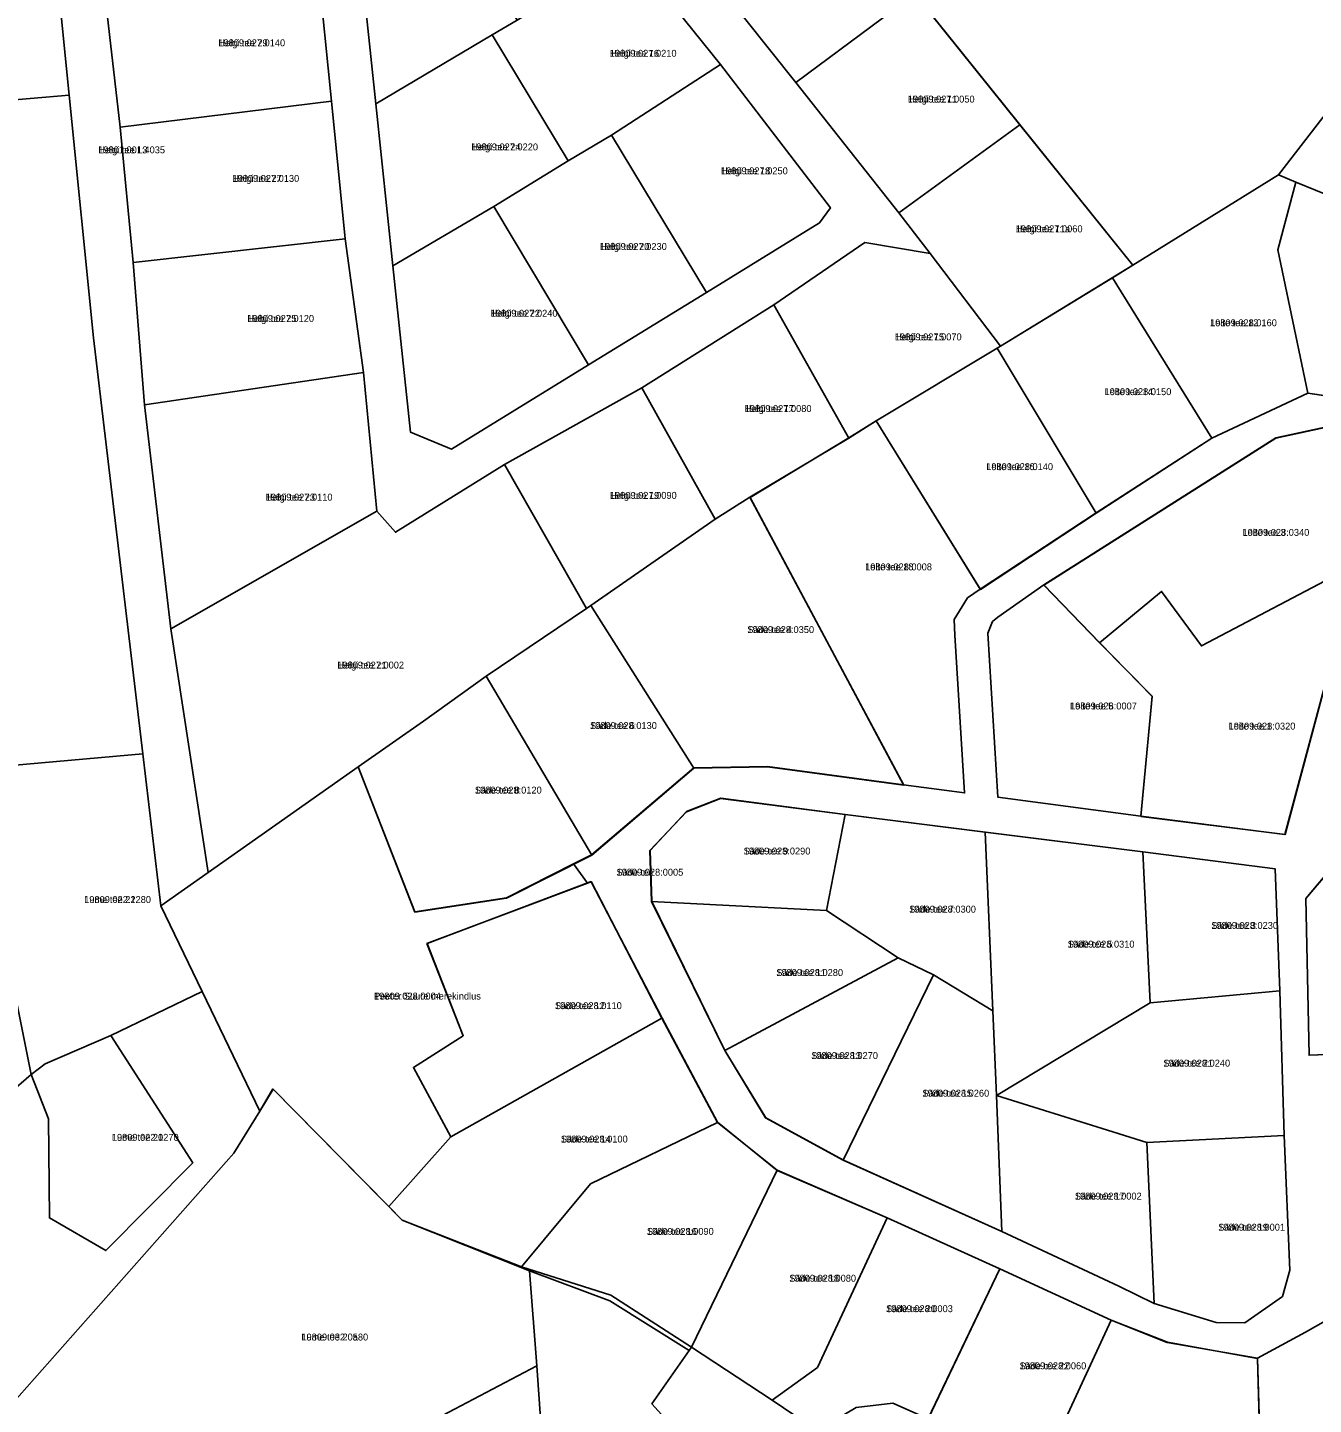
# Model space of a CAD drawing. Extents: x 516875 to 535633, y 6574491 to 6593094.
# Drawn here: x 521368.5 to 521647.7, y 6588659.7 to 6588958.5 of the extents above; entities that cross this region are included whole.
import ezdxf

# ---------------------------------------------------------------- set-up
doc = ezdxf.new("R2010")
doc.units = 0
for name, color, linetype in [('L_AADRESS', 7, 'Continuous'), ('PIIR', 7, 'Continuous'), ('TUNNUS', 7, 'Continuous')]:
    doc.layers.add(name, color=color, linetype=linetype)

msp = doc.modelspace()

# ---------------------------------------------------------------- linework, layer by layer
at = {"layer": 'PIIR'}
for points in [[(521590.91, 6589055.48), (521789.03, 6589241.93), (521800.17, 6589148.45), (521810.31, 6589063.39), (521810.89, 6589058.49), (521811.01, 6589057.49), (521738.69, 6588991.11), (521708.09, 6588956.45), (521702.42, 6588942.89), (521703.42, 6588925.56), (521710, 6588903.9), (521716.38, 6588894.74), (521673.79, 6588912.85), (521643.87, 6588925), (521640.14, 6588926.57), (521679.87, 6588978)], [(521359.99, 6589121.35), (521369.78, 6589120.47), (521372.96, 6589085.92), (521375.98, 6589055.84), (521381.13, 6589006.85), (521385.13, 6588967.12), (521388.61, 6588936.89), (521391.48, 6588907.51), (521393.88, 6588876.62), (521399.64, 6588828.05), (521407.72, 6588775.12), (521397.43, 6588767.88), (521393.53, 6588800.89), (521382.85, 6588891.18), (521377.57, 6588943.82), (521367.14, 6589047.69), (521365.58, 6589063.75)], [(521411.39, 6589116.77), (521436.47, 6589114.49), (521425.81, 6589100.81), (521428.46, 6589081.13), (521444.8, 6589060.34), (521467.91, 6589031.48), (521513.02, 6588974.62), (521535.33, 6588946.59), (521557.66, 6588918.34), (521564.46, 6588909.48), (521550.3, 6588911.88), (521530.56, 6588898.36), (521501.87, 6588880.36), (521472.1, 6588863.7), (521448.37, 6588849), (521444.33, 6588853.58), (521441.46, 6588883.67), (521437.48, 6588912.65), (521434.48, 6588942.56), (521431.53, 6588972.03), (521427.11, 6589012.43), (521422.52, 6589062.36), (521416.06, 6589093.87)], [(521432.07, 6589055.98), (521437.89, 6589000.93), (521444.12, 6588941.97), (521447.83, 6588906.81), (521451.64, 6588870.73), (521460.6, 6588867.04), (521490.33, 6588885.31), (521515.9, 6588901.02), (521540.48, 6588916.12), (521542.82, 6588919.42), (521518.97, 6588950.53), (521499.43, 6588974.81)], [(521526.07, 6589009.51), (521590.91, 6589055.48), (521679.87, 6588978), (521640.14, 6588926.57), (521608.51, 6588906.92)], [(521306.57, 6589051.13), (521305.68, 6589046.1), (521350.97, 6589047.31), (521367.14, 6589047.69), (521377.57, 6588943.82), (521360.53, 6588942.38), (521323.71, 6588953.19), (521318.95, 6588968.03), (521312.79, 6588965.96), (521301.69, 6589000.55), (521292.02, 6589012.37), (521274.46, 6589008.21), (521266.3, 6589048.24)], [(521469.37, 6588956.92), (521444.12, 6588941.97), (521437.89, 6589000.93), (521448.33, 6589003.56), (521474.81, 6588960.14)], [(521513.02, 6588974.62), (521538.41, 6588994.17), (521561.13, 6588965.84), (521535.33, 6588946.59)], [(521469.37, 6588956.92), (521474.81, 6588960.14), (521499.43, 6588974.81), (521518.97, 6588950.53), (521495.33, 6588935.2), (521485.91, 6588929.57)], [(521385.13, 6588967.12), (521431.53, 6588972.03), (521434.48, 6588942.56), (521388.61, 6588936.89)], [(521535.33, 6588946.59), (521561.13, 6588965.84), (521583.95, 6588937.4), (521557.66, 6588918.34)], [(521469.72, 6588919.66), (521447.83, 6588906.81), (521444.12, 6588941.97), (521469.37, 6588956.92), (521485.91, 6588929.57)], [(521542.82, 6588919.42), (521540.48, 6588916.12), (521515.9, 6588901.02), (521495.33, 6588935.2), (521518.97, 6588950.53)], [(521388.61, 6588936.89), (521434.48, 6588942.56), (521437.48, 6588912.65), (521391.48, 6588907.51)], [(521490.33, 6588885.31), (521469.72, 6588919.66), (521485.91, 6588929.57), (521495.33, 6588935.2), (521515.9, 6588901.02)], [(521564.46, 6588909.48), (521557.66, 6588918.34), (521583.95, 6588937.4), (521608.51, 6588906.92), (521579.74, 6588889.36)], [(521604.08, 6588904.23), (521608.51, 6588906.92), (521640.14, 6588926.57), (521643.87, 6588925), (521639.99, 6588910.31), (521646.47, 6588879.15), (521625.68, 6588869.42)], [(521639.99, 6588910.31), (521643.87, 6588925), (521673.79, 6588912.85), (521669.52, 6588901.71), (521667.19, 6588897.03), (521660, 6588877.16), (521646.47, 6588879.15)], [(521460.6, 6588867.04), (521451.64, 6588870.73), (521447.83, 6588906.81), (521469.72, 6588919.66), (521490.33, 6588885.31)], [(521391.48, 6588907.51), (521437.48, 6588912.65), (521441.46, 6588883.67), (521393.88, 6588876.62)], [(521546.83, 6588869.4), (521530.56, 6588898.36), (521550.3, 6588911.88), (521564.46, 6588909.48), (521579.74, 6588889.36), (521552.77, 6588873.18)], [(521579.05, 6588888.94), (521579.74, 6588889.36), (521604.08, 6588904.23), (521625.68, 6588869.42), (521600.56, 6588853.15)], [(521501.87, 6588880.36), (521530.56, 6588898.36), (521546.83, 6588869.4), (521525.34, 6588856.59), (521517.81, 6588851.8)], [(521579.05, 6588888.94), (521600.56, 6588853.15), (521575.4, 6588836.59), (521552.77, 6588873.18)], [(521441.46, 6588883.67), (521444.33, 6588853.58), (521399.64, 6588828.05), (521393.88, 6588876.62)], [(521489.85, 6588832.46), (521472.1, 6588863.7), (521501.87, 6588880.36), (521517.81, 6588851.8)], [(521525.38, 6588856.55), (521546.8, 6588869.5), (521552.8, 6588873.14), (521575.38, 6588836.66), (521572.61, 6588834.75), (521569.68, 6588830.02), (521569.88, 6588826.68), (521571.96, 6588792.41), (521558.73, 6588794.15)], [(521577.05, 6588827.11), (521579.21, 6588791.46), (521610.2, 6588787.38), (521641.5, 6588783.41), (521657.29, 6588842.15), (521662.14, 6588866.39), (521651.9, 6588872.14), (521639.52, 6588869.47), (521589.17, 6588837.56), (521579.18, 6588830.58), (521578.05, 6588829.6)], [(521614.73, 6588836.16), (521601.26, 6588825), (521589.2, 6588837.49), (521639.54, 6588869.44), (521651.92, 6588872.12), (521662.16, 6588866.37), (521657.31, 6588842.13), (521623.4, 6588824.31)], [(521444.33, 6588853.58), (521448.37, 6588849), (521472.1, 6588863.7), (521489.85, 6588832.46), (521468.09, 6588817.74), (521454.49, 6588808), (521440.28, 6588798.05), (521407.72, 6588775.12), (521399.64, 6588828.05)], [(521490.8, 6588833.12), (521517.81, 6588851.8), (521525.34, 6588856.59), (521558.79, 6588794.07), (521529.21, 6588798.04), (521513.2, 6588797.81)], [(521641.54, 6588783.37), (521610.26, 6588787.33), (521612.66, 6588813.39), (521601.26, 6588825), (521614.73, 6588836.16), (521623.4, 6588824.31), (521657.31, 6588842.13)], [(521577.05, 6588827.11), (521578.05, 6588829.6), (521579.18, 6588830.58), (521589.17, 6588837.56), (521601.3, 6588825), (521612.69, 6588813.36), (521610.2, 6588787.38), (521579.21, 6588791.46)], [(521489.85, 6588832.46), (521490.8, 6588833.12), (521513.2, 6588797.81), (521491.02, 6588778.91), (521468.09, 6588817.74)], [(521491.02, 6588778.91), (521472.54, 6588769.6), (521452.63, 6588766.54), (521440.28, 6588798.05), (521454.46, 6588807.99), (521468.09, 6588817.74)], [(521372.37, 6588733.63), (521369.27, 6588731.29), (521359.98, 6588777.57), (521355.22, 6588797.52), (521393.53, 6588800.89), (521397.43, 6588767.88), (521406.4, 6588749.3), (521386.6, 6588739.78)], [(521397.43, 6588767.88), (521407.72, 6588775.12), (521440.28, 6588798.05), (521452.61, 6588766.58), (521472.5, 6588769.67), (521487.08, 6588777.01), (521490.07, 6588772.84), (521455.24, 6588759.7), (521463.13, 6588739.7), (521452.28, 6588732.83), (521460.45, 6588717.77), (521446.98, 6588702.68), (521421.8, 6588728.17), (521418.94, 6588723.37), (521406.4, 6588749.3)], [(521503.62, 6588779.92), (521511.57, 6588788.32), (521519, 6588791.23), (521546.01, 6588787.73), (521541.99, 6588766.88), (521504.02, 6588768.83)], [(521503.67, 6588779.95), (521504.05, 6588768.86), (521519.92, 6588736.52), (521528.81, 6588721.93), (521545.64, 6588712.71), (521580.02, 6588697.24), (521605.49, 6588685.36), (521613.14, 6588681.58), (521626.57, 6588677.47), (521632.85, 6588677.42), (521641.02, 6588683.14), (521642.57, 6588688.8), (521641.35, 6588718.07), (521640.44, 6588749.43), (521639.42, 6588775.93), (521610.67, 6588779.61), (521576.48, 6588783.88), (521546.05, 6588787.74), (521519.04, 6588791.25), (521511.61, 6588788.35)], [(521557.58, 6588756.6), (521541.99, 6588766.88), (521546.01, 6588787.73), (521576.43, 6588783.88), (521578.13, 6588745.13), (521565.2, 6588752.91)], [(521578.13, 6588745.13), (521576.43, 6588783.88), (521610.64, 6588779.62), (521612.29, 6588746.83), (521578.9, 6588726.73)], [(521639.38, 6588775.96), (521640.41, 6588749.47), (521612.29, 6588746.83), (521610.64, 6588779.62)], [(521344.94, 6588771.8), (521359.98, 6588777.57), (521369.27, 6588731.29), (521364.46, 6588727.1), (521330.42, 6588734.26), (521334.54, 6588766.11)], [(521682.74, 6588774.72), (521682.56, 6588772.02), (521682.55, 6588762.98), (521683.71, 6588736.38), (521648.7, 6588735.54), (521646.75, 6588735.49), (521646.08, 6588769.53), (521651.82, 6588776.31)], [(521452.31, 6588732.82), (521463.11, 6588739.72), (521455.26, 6588759.73), (521490.88, 6588773.18), (521506.25, 6588743.51), (521460.42, 6588717.8)], [(521504.02, 6588768.83), (521541.99, 6588766.88), (521557.58, 6588756.6), (521519.88, 6588736.53)], [(521519.88, 6588736.53), (521557.58, 6588756.6), (521565.2, 6588752.91), (521545.6, 6588712.71), (521528.77, 6588721.9)], [(521578.13, 6588745.13), (521578.9, 6588726.73), (521580.02, 6588697.24), (521545.6, 6588712.71), (521565.2, 6588752.91)], [(521602.98, 6588719.25), (521578.9, 6588726.73), (521612.29, 6588746.83), (521640.41, 6588749.47), (521641.35, 6588718.07), (521611.51, 6588716.55)], [(521449.85, 6588699.7), (521446.95, 6588702.66), (521460.42, 6588717.8), (521506.25, 6588743.51), (521518.32, 6588720.88), (521490.75, 6588707.55), (521475.75, 6588689.57)], [(521404.37, 6588712.11), (521385.53, 6588693.09), (521373.28, 6588700.18), (521373.03, 6588721.65), (521369.27, 6588731.29), (521372.37, 6588733.63), (521386.6, 6588739.78)], [(521413.29, 6588714.19), (521418.94, 6588723.37), (521421.81, 6588728.14), (521449.85, 6588699.7), (521477.52, 6588688.69), (521479.07, 6588668.07), (521414.43, 6588634.08), (521384.67, 6588618.99), (521384.19, 6588619.81), (521361.62, 6588655.9)], [(521578.9, 6588726.73), (521602.98, 6588719.25), (521611.51, 6588716.55), (521613.14, 6588681.58), (521605.49, 6588685.36), (521580.02, 6588697.24)], [(521475.75, 6588689.57), (521490.75, 6588707.55), (521518.32, 6588720.88), (521531.26, 6588710.52), (521512.66, 6588672.12), (521495.17, 6588683.38)], [(521611.51, 6588716.55), (521641.35, 6588718.07), (521642.57, 6588688.8), (521641.02, 6588683.14), (521632.85, 6588677.42), (521626.57, 6588677.47), (521613.14, 6588681.58)], [(521512.66, 6588672.12), (521531.26, 6588710.52), (521555.15, 6588700.16), (521540.05, 6588667.74), (521530.2, 6588660.59)], [(521555.15, 6588700.16), (521579.64, 6588689.1), (521564.06, 6588656.54), (521556.42, 6588659.95), (521548.45, 6588659.06), (521537.94, 6588652.79), (521535.14, 6588657.27), (521530.2, 6588660.59), (521540.06, 6588667.73)], [(521486.87, 6588584.33), (521482.75, 6588615.48), (521479.07, 6588668.07), (521477.52, 6588688.69), (521494.97, 6588682.17), (521512.17, 6588671.42), (521504.07, 6588659.84), (521555.23, 6588603.22), (521567.46, 6588590.61), (521569.21, 6588585.96), (521555.19, 6588573.17), (521551.79, 6588559.93), (521542.52, 6588561.47), (521490.64, 6588555.41)], [(521579.64, 6588689.1), (521603.77, 6588677.97), (521589.89, 6588647.97), (521589.09, 6588645.14), (521564.01, 6588656.5)], [(521589.89, 6588647.97), (521603.77, 6588677.97), (521616, 6588673.19), (521635.59, 6588669.68), (521636.61, 6588632.74), (521622.12, 6588629.84), (521615.58, 6588634.3), (521589.09, 6588645.14)], [(521635.57, 6588669.71), (521645.98, 6588675.4), (521650.36, 6588677.81), (521657.98, 6588660.01), (521686.54, 6588663.79), (521687.16, 6588643.42), (521662.53, 6588638.23), (521636.65, 6588632.7)], [(521512.66, 6588672.12), (521530.2, 6588660.59), (521535.14, 6588657.27), (521537.94, 6588652.79), (521548.45, 6588659.06), (521556.42, 6588659.95), (521564.06, 6588656.54), (521589.16, 6588645.12), (521593.39, 6588643.38), (521589.51, 6588639.54), (521555.23, 6588603.22), (521504.07, 6588659.84)], [(521402.26, 6588595.47), (521414.43, 6588634.08), (521479.07, 6588668.07), (521482.75, 6588615.48), (521486.87, 6588584.33), (521476.87, 6588585.59), (521415.82, 6588593.57)]]:
    msp.add_lwpolyline(points, close=True, dxfattribs=at)
for points in [[(521360.53, 6588942.38), (521377.57, 6588943.82), (521382.85, 6588891.18), (521393.53, 6588800.89), (521355.22, 6588797.52)], [(521650.36, 6588677.81), (521645.98, 6588675.4), (521635.57, 6588669.71), (521615.98, 6588673.16), (521603.78, 6588678.01), (521579.64, 6588689.1), (521555.15, 6588700.16), (521531.26, 6588710.48), (521518.34, 6588720.92), (521506.29, 6588743.49), (521490.87, 6588773.14), (521490.07, 6588772.84), (521487.08, 6588777.01), (521490.98, 6588778.98), (521513.15, 6588797.89), (521529.16, 6588798.13), (521558.73, 6588794.15), (521571.96, 6588792.41), (521569.88, 6588826.68), (521569.68, 6588830.02), (521572.61, 6588834.75), (521575.38, 6588836.66), (521600.54, 6588853.19), (521625.67, 6588869.44), (521646.47, 6588879.18), (521659.98, 6588877.2)], [(521651.8, 6588776.32), (521646.05, 6588769.53), (521646.77, 6588735.5), (521648.71, 6588735.56)], [(521364.46, 6588727.1), (521369.27, 6588731.29), (521373.03, 6588721.65), (521373.28, 6588700.18), (521385.53, 6588693.09), (521404.37, 6588712.11), (521386.6, 6588739.78), (521406.4, 6588749.3), (521418.94, 6588723.37), (521413.29, 6588714.19), (521361.62, 6588655.9)]]:
    msp.add_lwpolyline(points, dxfattribs=at)

# ---------------------------------------------------------------- texts
at = {"layer": 'L_AADRESS'}
for s, p in [('Helgi tee 29', (521409.94, 6588954.46)), ('Helgi tee 16', (521494.93, 6588952.19)), ('Helgi tee 11', (521559.64, 6588942.25)), ('Helgi tee L3', (521383.86, 6588931.23)), ('Helgi tee 24', (521464.85, 6588931.87)), ('Helgi tee 27', (521413, 6588925.04)), ('Helgi tee 18', (521519.07, 6588926.68)), ('Helgi tee 11a', (521583.08, 6588914.09)), ('Helgi tee 20', (521492.81, 6588910.26)), ('Helgi tee 25', (521416.22, 6588894.63)), ('Helgi tee 22', (521469.08, 6588895.77)), ('Loite tee 12', (521625.27, 6588893.7)), ('Helgi tee 15', (521556.83, 6588890.64)), ('Loite tee 14', (521602.36, 6588878.75)), ('Helgi tee 17', (521524.23, 6588875.08)), ('Loite tee 16', (521576.67, 6588862.47)), ('Helgi tee 23', (521420.23, 6588855.86)), ('Helgi tee 19', (521494.96, 6588856.24)), ('Loite tee 3', (521632.31, 6588848.21)), ('Loite tee 18', (521550.38, 6588840.72)), ('Säde tee 4', (521524.79, 6588827.11)), ('Helgi tee 21', (521435.76, 6588819.41)), ('Loite tee 5', (521594.87, 6588810.53)), ('Säde tee 6', (521490.65, 6588806.28)), ('Loite tee 1', (521629.29, 6588806.16)), ('Säde tee 8', (521465.65, 6588792.27)), ('Säde tee 9', (521523.99, 6588779.05)), ('Säde tee', (521496.39, 6588774.45)), ('Lume tee 22', (521380.81, 6588768.52)), ('Säde tee 7', (521559.93, 6588766.43)), ('Säde tee 3', (521625.52, 6588762.9)), ('Säde tee 5', (521594.36, 6588758.84)), ('Säde tee 11', (521531.08, 6588752.68)), ('Peeter Suure merekindlus', (521443.75, 6588747.57)), ('Säde tee 12', (521483.04, 6588745.49)), ('Säde tee 13', (521538.66, 6588734.66)), ('Säde tee 21', (521615.12, 6588733.01)), ('Säde tee 15', (521562.81, 6588726.49)), ('Lume tee 20', (521386.82, 6588716.91)), ('Säde tee 14', (521484.32, 6588716.54)), ('Säde tee 17', (521595.92, 6588704.15)), ('Säde tee 19', (521627.04, 6588697.4)), ('Säde tee 16', (521503, 6588696.5)), ('Säde tee 18', (521533.9, 6588686.33)), ('Säde tee 20', (521554.92, 6588679.72)), ('Lume tee 20a', (521427.97, 6588673.57)), ('Säde tee 22', (521583.89, 6588667.32))]:
    msp.add_text(s, height=1.5, dxfattribs=at).set_placement(p)
at = {"layer": 'TUNNUS'}
for s, p in [('19809:027:0140', (521409.94, 6588954.46)), ('19809:027:0210', (521494.93, 6588952.19)), ('19809:027:0050', (521559.64, 6588942.25)), ('19801:001:4035', (521383.86, 6588931.23)), ('19809:027:0220', (521464.85, 6588931.87)), ('19809:027:0130', (521413, 6588925.04)), ('19809:027:0250', (521519.07, 6588926.68)), ('19809:027:0060', (521583.08, 6588914.09)), ('19809:027:0230', (521492.81, 6588910.26)), ('19809:027:0120', (521416.22, 6588894.63)), ('19809:027:0240', (521469.08, 6588895.77)), ('19809:028:0160', (521625.27, 6588893.7)), ('19809:027:0070', (521556.83, 6588890.64)), ('19809:028:0150', (521602.36, 6588878.75)), ('19809:027:0080', (521524.23, 6588875.08)), ('19809:028:0140', (521576.67, 6588862.47)), ('19809:027:0110', (521420.23, 6588855.86)), ('19809:027:0090', (521494.96, 6588856.24)), ('19809:028:0340', (521632.31, 6588848.21)), ('19809:028:0008', (521550.38, 6588840.72)), ('19809:028:0350', (521524.79, 6588827.11)), ('19809:027:0002', (521435.76, 6588819.41)), ('19809:028:0007', (521594.87, 6588810.53)), ('19809:028:0130', (521490.65, 6588806.28)), ('19809:028:0320', (521629.29, 6588806.16)), ('19809:028:0120', (521465.65, 6588792.27)), ('19809:028:0290', (521523.99, 6588779.05)), ('19809:028:0005', (521496.39, 6588774.45)), ('19809:022:1280', (521380.81, 6588768.52)), ('19809:028:0300', (521559.93, 6588766.43)), ('19809:028:0230', (521625.52, 6588762.9)), ('19809:028:0310', (521594.36, 6588758.84)), ('19809:028:0280', (521531.08, 6588752.68)), ('19809:028:0004', (521443.75, 6588747.57)), ('19809:028:0110', (521483.04, 6588745.49)), ('19809:028:0270', (521538.66, 6588734.66)), ('19809:028:0240', (521615.12, 6588733.01)), ('19809:028:0260', (521562.81, 6588726.49)), ('19809:022:1270', (521386.82, 6588716.91)), ('19809:028:0100', (521484.32, 6588716.54)), ('19809:028:0002', (521595.92, 6588704.15)), ('19809:028:0001', (521627.04, 6588697.4)), ('19809:028:0090', (521503, 6588696.5)), ('19809:028:0080', (521533.9, 6588686.33)), ('19809:028:0003', (521554.92, 6588679.72)), ('19809:032:0580', (521427.97, 6588673.57)), ('19809:028:0060', (521583.89, 6588667.32))]:
    msp.add_text(s, height=1.5, dxfattribs=at).set_placement(p)

doc.saveas('drawing.dxf')
